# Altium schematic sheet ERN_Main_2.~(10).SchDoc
size A; SheetNumber: 2; SheetTotal: 3; SPICEModelCacheYVUKJMZF: <root> / <DocumentId>YVUKJMZF</DocumentId> / <CacheFrame Number="0"> / <Model Name="1n5400" Kind="MDL"> / <Text>*1N5400 MCE / * 50V 3A Si Rectifier pkg:DO-201 1,2 / .MODEL 1N5400 D(IS=2.68E-12 RS=0.00977 N=1.17 TT=1.44E-5 CJO=1.24E-10 / + VJ=0.6 M=0.333 BV=66.6 IBV=1E-5 )</Text> / </Model> / <Model Name="led2" Kind="MDL"> / <Text>*Typ RED,GREEN,YELLOW,AMBER GaAs LED: Vf=2.1V Vr=4V If=40mA trr=3uS / *LED Pinout: 1=A, 2=K / .MODEL LED2 D (IS=93.1P RS=42M N=4.61 BV=4 IBV=10U / + CJO=2.97P VJ=.75 M=.333 TT=4.32U)</Text> / </Model> / </CacheFrame> / </root>
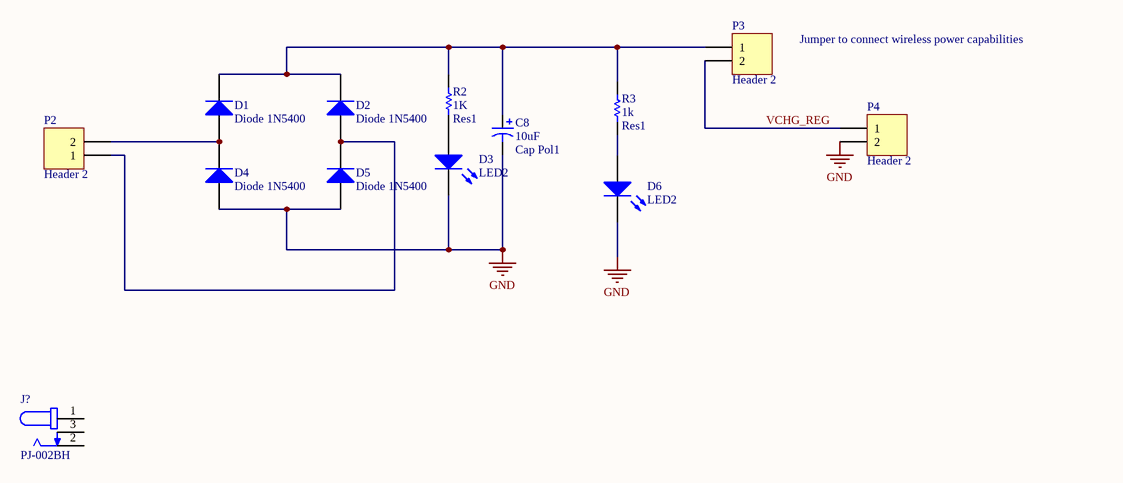
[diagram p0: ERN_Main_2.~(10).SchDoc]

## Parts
C8  Cap Pol1  value 10uF  [RB7.6-15]
D1  Diode 1N5400  [DO-201AD]
D2  Diode 1N5400  [DO-201AD]
D3  LED2  [3.2X1.6X1.1]
D4  Diode 1N5400  [DO-201AD]
D5  Diode 1N5400  [DO-201AD]
D6  LED2  [3.2X1.6X1.1]
J?  PJ-002BH  [CUI_PJ-002BH]
P2  Header 2  [HDR1X2]
P3  Header 2  [HDR1X2]
P4  Header 2  [HDR1X2]
R2  Res1  value 1K  [AXIAL-0.3]
R3  Res1  value 1k  [AXIAL-0.3]

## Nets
GND: C8.2 D3.2(K) D4.1(A) D5.1(A) D6.2(K) P4.2
VCHG_REG: P3.2 P4.1
NetC8_1: C8.1 D1.2(K) D2.2(K) P3.1 R2.2 R3.2
NetD1_1: D1.1(A) D4.2(K) P2.2
NetD2_1: D2.1(A) D5.2(K) P2.1
NetD3_1: D3.1(A) R2.1
NetD6_1: D6.1(A) R3.1

Not connected (* = marked no-connect by the designer): J? 1 2 3

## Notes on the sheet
- Jumper to connect wireless power capabilities

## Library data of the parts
C8 = Cap Pol1: Polarized Capacitor (Radial)
D1 D2 D4 D5 = Diode 1N5400: 3 Amp General Purpose Rectifier
D3 D6 = LED2: Typical RED, GREEN, YELLOW, AMBER GaAs LED
J? = PJ-002BH: 2.5 x 6.5 mm, 5.0 A, Horizontal, Through Hole, Dc Power Jack Connector; MF: Same Sky
P2-P4 = Header 2: Header, 2-Pin
R2 R3 = Res1: Resistor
